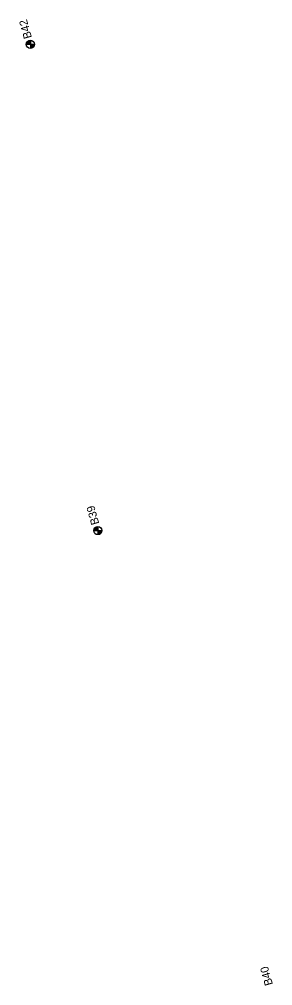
# Model space of a CAD drawing. Extents: x 345549 to 379569, y 127949 to 230467.
# Drawn here: x 360562 to 360873, y 150411 to 151596 of the extents above; entities that cross this region are included whole.
import ezdxf

# ---------------------------------------------------------------- set-up
doc = ezdxf.new("R2010")
doc.units = 0
for name, color, linetype in [('E_SOIL_BORE1 [KAPUR_CADDS_LEVELS]', 7, 'Continuous'), ('E_SOIL_BORE2 [KAPUR_CADDS_LEVELS]', 7, 'Continuous'), ('P_MARK', 7, 'Continuous')]:
    doc.layers.add(name, color=color, linetype=linetype)

msp = doc.modelspace()

# ---------------------------------------------------------------- linework, layer by layer
at = {"layer": 'P_MARK'}
for p, q in [((360570.2, 151565.4), (360580.2, 151565.4)), ((360575.2, 151570.4), (360575.2, 151560.4)), ((360658, 150974), (360658, 150964)), ((360653, 150969), (360663, 150969))]:
    msp.add_line(p, q, dxfattribs=at)
for centre in [(360575.2, 151565.4), (360658, 150969)]:
    msp.add_circle(centre, 5, dxfattribs=at)
for centre, radius, start, end in [((360575.2, 151565.4), 4.5, 89.9869, 179.9869), ((360575.2, 151565.4), 4, 89.9869, 179.9869), ((360575.2, 151565.4), 3.5, 89.9869, 179.9869), ((360575.2, 151565.4), 3, 89.9869, 179.9869), ((360575.2, 151565.4), 2.5, 89.9869, 179.9869), ((360575.2, 151565.4), 2, 89.9869, 179.9869), ((360575.2, 151565.4), 1.5, 89.9869, 179.9869), ((360575.2, 151565.4), 1, 89.9869, 179.9869), ((360575.2, 151565.4), 0.5, 89.9869, 179.9869), ((360575.2, 151565.4), 4.5, 269.9869, 359.9869), ((360575.2, 151565.4), 4, 269.9869, 359.9869), ((360575.2, 151565.4), 3.5, 269.9869, 359.9869), ((360575.2, 151565.4), 3, 269.9869, 359.9869), ((360575.2, 151565.4), 2.5, 269.9869, 359.9869), ((360575.2, 151565.4), 2, 269.9869, 359.9869), ((360575.2, 151565.4), 1.5, 269.9869, 359.9869), ((360575.2, 151565.4), 1, 269.9869, 359.9869), ((360575.2, 151565.4), 0.5, 269.9869, 359.9869), ((360658, 150969), 4.5, 89.9869, 179.9869), ((360658, 150969), 4, 89.9869, 179.9869), ((360658, 150969), 3.5, 89.9869, 179.9869), ((360658, 150969), 3, 89.9869, 179.9869), ((360658, 150969), 2.5, 89.9869, 179.9869), ((360658, 150969), 2, 89.9869, 179.9869), ((360658, 150969), 1.5, 89.9869, 179.9869), ((360658, 150969), 1, 89.9869, 179.9869), ((360658, 150969), 0.5, 89.9869, 179.9869), ((360658, 150969), 4.5, 269.9869, 359.9869), ((360658, 150969), 4, 269.9869, 359.9869), ((360658, 150969), 3.5, 269.9869, 359.9869), ((360658, 150969), 3, 269.9869, 359.9869), ((360658, 150969), 2.5, 269.9869, 359.9869), ((360658, 150969), 2, 269.9869, 359.9869), ((360658, 150969), 1.5, 269.9869, 359.9869), ((360658, 150969), 1, 269.9869, 359.9869), ((360658, 150969), 0.5, 269.9869, 359.9869)]:
    msp.add_arc(centre, radius, start, end, dxfattribs=at)

# ---------------------------------------------------------------- texts
at = {"layer": 'E_SOIL_BORE1 [KAPUR_CADDS_LEVELS]'}
msp.add_text('B40', height=10, rotation=105.7466, dxfattribs=at).set_placement((360873.1, 150412.5))
at = {"layer": 'E_SOIL_BORE2 [KAPUR_CADDS_LEVELS]'}
for s, p in [('B42', (360577.2, 151573.8)), ('B39', (360659.9, 150977.6))]:
    msp.add_text(s, height=10, rotation=105.7466, dxfattribs=at).set_placement(p)

doc.saveas('drawing.dxf')
